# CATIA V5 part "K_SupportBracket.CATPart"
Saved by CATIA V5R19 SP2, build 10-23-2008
Part number: Support Bracket
Bounding box of the stored display mesh (mm): x -42 to 42, y -5 to 5, z -6 to 8.991
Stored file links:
  G:\Khaled_CFAO_2011\ST2M\ST2M_GR1\bgaltie\bgaltie\Khaled\CAD_thinkMOTION\K_SupportBracket.CATPart
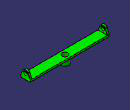
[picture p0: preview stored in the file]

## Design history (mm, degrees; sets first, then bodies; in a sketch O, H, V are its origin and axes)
AxisSystem1: origin (0, 0, 0), X (1, 0, 0), Y (0, 1, 0), Z (0, 0, 1)
Body1 (main body)
  Sketch1 on YZ plane of AxisSystem1, origin (0, 0, 0), H (0, 1, 0), V (0, 0, 1)
    point P1 (-5, 2)
    line L1 (5, 2) -> (5, 0)
    line L2 (5, 0) -> (-5, 0)
    line L3 (-5, 0) -> (-5, 2)
    point P2 (5, 2)
    reference intersected line E1 through (0, 0) direction (0, 1) from ZX plane of AxisSystem1
    circle A1 centre (0, 6) radius 2
    point P5 (0, 6)
    reference projected line E2 through (0, 0) direction (0, 1) from edge [ZX plane of AxisSystem1 | YZ plane of AxisSystem1]
    arc A2 centre (0, 6) radius 3 from (2.7532, 7.1915) to (-2.7532, 7.1915) ccw
    point P6 (0, 6)
    line L4 (-5, 2) -> (-2.7532, 7.1915)
    point P7 (-5, 2)
    line L5 (5, 2) -> (2.7532, 7.1915)
    point P9 (5, 2)
    length L1 = 2
    length L2 = 10
    radius A1 = 2
    distance P5 L2 = 6
    radius A2 = 3
    length L3 = 2
    horizontal: L2 H
    vertical: L1 V, L3 V
    coincidence: L2 H, P5 E2, P6 P5, P7 P1, P9 P2
    symmetry: L1 L3 E1
    tangency: L4 A2, L5 A2
  Pad1: profile Sketch1, direction (-1, 0, 0), length 42, mirrored extent
  Sketch2 on face of Pad1 from Sketch1.L1, origin (0, 5, 0), H (-1, 0, 0), V (0, 0, 1)
    line L1 (-40, 13.7186) -> (40, 13.7186)
    line L2 (40, 13.7186) -> (40, 2)
    line L3 (40, 2) -> (-40, 2)
    line L4 (-40, 2) -> (-40, 13.7186)
    reference projected line E1 (-27, 2) -> (27, 2) from edge [face of Pad1 from Sketch1.L1 | face of Pad1 from Sketch1.L5]
    reference projected line E2 (42, 2) -> (42, 7.5776) from edge [end face of Pad1 | face of Pad1 from Sketch1.L5]
    reference projected line E3 (-42, 2) -> (-42, 7.5776) from edge [face of Pad1 from Sketch1.L5 | start face of Pad1]
    distance L2 E2 = 2
    distance L4 E3 = 2
    horizontal: L1 H, L3 H
    vertical: L2 V, L4 V
    coincidence: L3 E1
  Pocket1: profile Sketch2, direction (0, -1, 0), through (limit type 6)
  Sketch3 on face of Pad1 from Sketch1.L2, origin (0, 0, 0), H (1, 0, 0), V (0, -1, 0)
    circle A1 centre (0, 0) radius 4
    point P1 (0, 0)
    radius A1 = 4
    coincidence: P1 O
  Pad2: profile Sketch3, direction (0, 0, -1), length 6
  Sketch4 on face of Pocket1 from Sketch2.L3, origin (-1.865, 2.2966, 2), H (1, 0, 0), V (0, 1, 0)
    point P1 (1.865, -2.2966)
    reference projected point E1 (1.865, -2.2966) from vertex [YZ plane of AxisSystem1 | ZX plane of AxisSystem1 | XY plane of AxisSystem1]
    coincidence: P1 E1
  Hole1: placed by Sketch4, at (0, 0, 2) direction (0, 0, -1), diameter 6, depth 6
